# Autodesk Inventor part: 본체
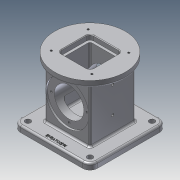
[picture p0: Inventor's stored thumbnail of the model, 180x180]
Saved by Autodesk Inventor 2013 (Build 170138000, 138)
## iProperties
Created: 2021-05
Part Number: 본체
Material: 알루미늄 6061
Document SubType Name: Modeling
Designer: a
Density: 2.71 g/cm^3
Mass: 1256.24 g
Surface Area: 895.285 cm^2
Volume: 463.556 cm^3
Author: a
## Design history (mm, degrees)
sketch "스케치1"
  geometry: L1 (62.5, -62.5)-(-62.5, -62.5); L2 (-62.5, -62.5)-(-62.5, 62.5); L3 (-62.5, 62.5)-(62.5, 62.5); L4 (62.5, 62.5)-(62.5, -62.5); L5 (62.5, -62.5)-(-62.5, 62.5); L6 (-62.5, -62.5)-(62.5, 62.5); 1 further point
  constraints: 12 end point, 2 midpoint, 2 parallel, 1 horizontal, 1 perpendicular
  dimensions: "d0" = 125 distance of L2.end L3.end; "d1" = 125 distance of L1.end L2.end
extrude "돌출1" new body sketch "스케치1" distance "d2" = 10; taper "d3" = 0 deg
sketch "스케치2"
  geometry: L1 (-37, 37)-(37, 37); L2 (37, 37)-(37, -37); L3 (37, -37)-(-37, -37); L4 (-37, -37)-(-37, 37); L5 (-37, 37)-(37, -37); L6 (37, 37)-(-37, -37); 1 further point
  constraints: 12 end point, 2 midpoint, 2 parallel, 1 horizontal, 1 perpendicular
  dimensions: "d4" = 74 distance of L2.end L3.end; "d5" = 74 distance of L1.end L2.end
extrude "돌출2" join sketch "스케치2" distance "d6" = 88; taper "d7" = 0 deg
sketch "스케치3"
  geometry: C1 r 57.5 at (0, 0); 1 further point
  constraints: 1 centre point, 1 coincident
  dimensions: "d8" = 115 diameter of C1
extrude "돌출3" join sketch "스케치3" distance "d9" = 10; taper "d10" = 0 deg
sketch "스케치4"
  geometry: L1 (-26, 26)-(26, 26); L2 (26, 26)-(26, -26); L3 (26, -26)-(-26, -26); L4 (-26, -26)-(-26, 26); L5 (-26, 26)-(26, -26); L6 (26, 26)-(-26, -26); C1 r 57.5 at (0, 0) reference
  constraints: 12 end point, 2 midpoint, 2 parallel, 1 horizontal, 1 perpendicular
  dimensions: "d11" = 52 distance of L2.end L3.end; "d12" = 52 distance of L1.end L2.end
extrude "돌출4" cut sketch "스케치4" distance "d13" = 8; taper "d14" = 0 deg
sketch "스케치5"
  geometry: L1 (-22, 22)-(22, 22); L2 (22, 22)-(22, -22); L3 (22, -22)-(-22, -22); L4 (-22, -22)-(-22, 22); L5 (-22, 22)-(22, -22); L6 (22, 22)-(-22, -22); 1 further point
  constraints: 12 end point, 2 midpoint, 2 parallel, 1 horizontal, 1 perpendicular
  dimensions: "d15" = 44 distance of L2.end L3.end; "d16" = 44 distance of L1.end L2.end
extrude "돌출5" cut sketch "스케치5" distance "d17" = 74; taper "d18" = 0 deg
sketch "스케치8"
  geometry: L1 (0, 0)-(0, 88) reference; L2 (37, -10)-(37, 44); C1 r 35 at (37, 44)
  constraints: 2 end point, 1 centre point, 1 coincident, 1 parallel
  dimensions: "d23" = 54 distance of L2.start L2.end; "d24" = 70 diameter of C1
extrude "돌출6" cut sketch "스케치8" distance "d25" = 3; taper "d26" = 0 deg
sketch "스케치9"
  geometry: C1 r 35 at (0, 0) reference; C2 r 24 at (0, 0); 1 further point
  constraints: 1 centre point, 1 coincident
  dimensions: "d27" = 48 diameter of C2
extrude "돌출7" cut sketch "스케치9" stored distance "d28" = 0; taper "d29" = 0 deg
sketch "스케치10"
  geometry: C1 r 28 at (0, 0); 1 further point
  constraints: 1 centre point, 1 coincident
  dimensions: "d30" = 56 diameter of C1
extrude "돌출8" cut sketch "스케치10" distance "d31" = 18; taper "d32" = -10 deg
sketch "스케치11" dims "d33" = 58
  geometry: L1 (0, 0)-(0, 29); L2 (0, 0)-(-29, 0); L3 (0, 0)-(0, -29); L4 (0, 0)-(29, 0); C1 r 24 at (0, 0) reference; C2 r 35 at (0, 0) reference; 5 further points
  constraints: 8 end point, 5 coincident, 1 vertical, 1 vertical alignment, 19 other
  dimensions: "d36" = 360 deg dimension on C1.centre point (0, 29) (derived)
hole "구멍1" sketch "스케치11" at (0, 29), (-29, 0), (0, -29), (29, 0) diameter "d38" = 3.242; stored, may be unused: countersink angle "d42" = 82 deg, drill point angle "d44" = 118 deg; dims "d39" = 8, "d40" = 3.023, "d41" = 2, "d43" = 10
fillet "모깎기1" dims "d45" = 12
sketch "스케치12"
  geometry: L1 (0, 0)-(0, 88) reference; L2 (37, -10)-(37, 27); L3 (37, 27)-(37, 70); 1 further point
  constraints: 4 end point, 2 coincident, 1 collinear, 1 parallel
  dimensions: "d46" = 37 distance of L2.start L2.end; "d47" = 43 distance of L3.start L3.end
hole "구멍2" sketch "스케치12" at (37, 27), (37, 70) diameter "d48" = 4.134; stored, may be unused: countersink angle "d52" = 82 deg, drill point angle "d54" = 118 deg; dims "d49" = 20, "d50" = 3.023, "d51" = 2, "d53" = 20
sketch "스케치13"
  geometry: L1 (33, 30)-(-33, 30); L2 (-33, 30)-(-33, -30); L3 (-33, -30)-(33, -30); L4 (33, -30)-(33, 30); L5 (33, 30)-(-33, -30); L6 (-33, 30)-(33, -30); C1 r 57.5 at (0, 0) reference; 4 further points
  constraints: 12 end point, 4 coincident, 2 midpoint, 2 parallel, 1 horizontal, 1 perpendicular
  dimensions: "d55" = 66 distance of L3.end L2.end; "d56" = 60 distance of L2.end L1.end
hole "구멍3" sketch "스케치13" at (33, -30), (-33, -30), (-33, 30), (33, 30) diameter "d57" = 3.242; stored, may be unused: countersink angle "d61" = 82 deg, drill point angle "d63" = 118 deg; dims "d58" = 8, "d59" = 3.023, "d60" = 2, "d62" = 10
sketch "스케치14"
  geometry: A1 r 12 centre (50.5, -50.5) between (50.5, -62.5) and (62.5, -50.5) reference; A2 r 12 centre (50.5, 50.5) between (62.5, 50.5) and (50.5, 62.5) reference; A3 r 12 centre (-50.5, 50.5) between (-50.5, 62.5) and (-62.5, 50.5) reference; A4 r 12 centre (-50.5, -50.5) between (-62.5, -50.5) and (-50.5, -62.5) reference; 5 further points
  constraints: 4 coincident
hole "구멍4" sketch "스케치14" at (50.5, -50.5), (-50.5, -50.5), (-50.5, 50.5), (50.5, 50.5) diameter "d64" = 9; stored, may be unused: countersink angle "d68" = 82 deg, drill point angle "d70" = 118 deg; dims "d65" = 8, "d66" = 3.023, "d67" = 2, "d69" = 10
fillet "모깎기2" dims "d71" = 6
fillet "모깎기3" dims "d72" = 3
fillet "모깎기4" dims "d73" = 3
chamfer "모따기1" distance "d74" = 1; stored, may be unused: second distance "d75" = 2, angle "d76" = 45 deg
sketch "스케치15"
  geometry: 2 further points
  constraints: 1 vertical alignment, 1 other
  dimensions: "d77" = 55 distance of point (0, 55) point (0, 0)
feature "엠보싱1" sketch "스케치15" dims "d0" = 125, "d1" = 125, "d78" = 0.5, "d79" = 0
node "솔리드1"
mirror "대칭1"
mirror "대칭2"
